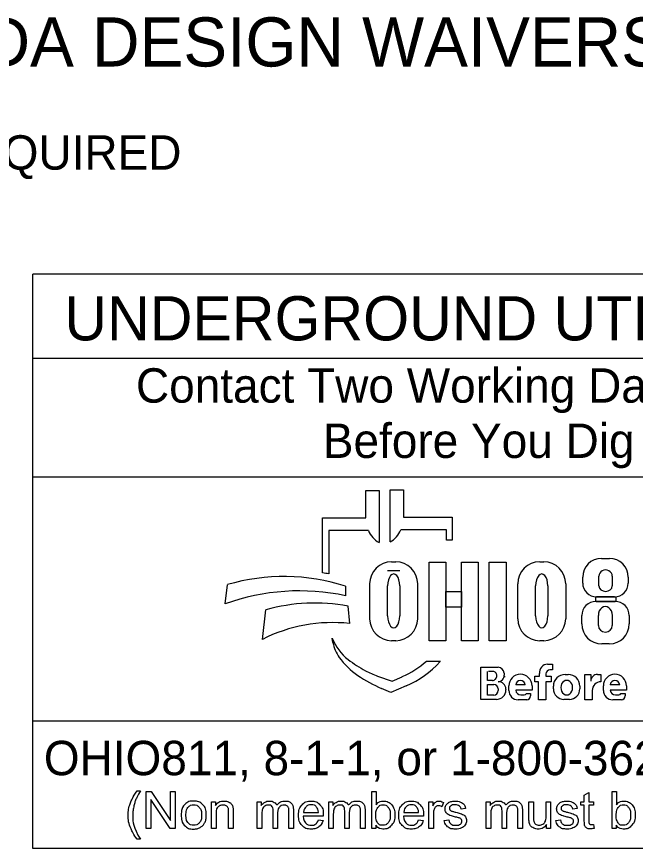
# Model space of a CAD drawing. Extents: x 0 to 34, y -2 to 22.
# Drawn here: x 2.311 to 4.831, y 2.143 to 5.529 of the extents above; entities that cross this region are included whole.
import ezdxf

# ---------------------------------------------------------------- set-up
doc = ezdxf.new("R2010")
doc.units = 0
doc.layers.add('SH_Data', color=7, linetype='Continuous')
doc.layers.add('SH_Text', color=7, linetype='Continuous')

msp = doc.modelspace()

# ---------------------------------------------------------------- linework, layer by layer
at = {"layer": 'SH_Data'}
for p, q in [((2.3775, 2.1428), (2.3775, 4.4803)), ((6.6275, 4.4803), (2.3775, 4.4803)), ((2.3775, 4.1387), (6.6275, 4.1387)), ((2.3775, 3.6553), (6.6275, 3.6553)), ((6.6275, 2.6607), (2.3775, 2.6607)), ((6.6275, 2.1428), (2.3775, 2.1428))]:
    msp.add_line(p, q, dxfattribs=at)
at = {"layer": 'SH_Text'}
for p, q in [((3.7335, 3.4883), (3.7335, 3.5998)), ((3.7335, 3.5998), (3.7872, 3.5998)), ((3.7872, 3.5998), (3.7872, 3.3877)), ((3.8329, 3.39), (3.8329, 3.6021)), ((3.8329, 3.6021), (3.8865, 3.6021)), ((3.8865, 3.6021), (3.8865, 3.4906)), ((3.5576, 3.2644), (3.5576, 3.4883)), ((3.5576, 3.4883), (3.7335, 3.4883)), ((3.8865, 3.4906), (4.0857, 3.4906)), ((4.0857, 3.4906), (4.0857, 3.3968)), ((3.5828, 3.4369), (3.5828, 3.26)), ((3.7439, 3.4369), (3.5828, 3.4369)), ((4.0625, 3.4392), (3.8761, 3.4392)), ((4.0625, 3.3968), (4.0625, 3.4392)), ((4.0857, 3.3968), (4.0625, 3.3968)), ((4.6931, 3.3231), (4.7258, 3.3231)), ((3.8385, 3.3091), (3.8551, 3.3091)), ((4.4416, 3.3091), (4.4581, 3.3091)), ((3.8718, 3.2721), (3.822, 3.2721)), ((4.683, 3.2111), (4.683, 3.2504)), ((4.7371, 3.2504), (4.7371, 3.2111)), ((3.7491, 3.0776), (3.7491, 3.2196)), ((3.9445, 3.2196), (3.9445, 3.0776)), ((4.3521, 3.0776), (4.3521, 3.2196)), ((4.5476, 3.2196), (4.5476, 3.0776)), ((4.6168, 3.2225), (4.6168, 3.2468)), ((4.8022, 3.2468), (4.8022, 3.2225)), ((3.1602, 3.1381), (3.1696, 3.2162)), ((3.6509, 3.2097), (3.6509, 3.1709)), ((3.822, 3.089), (3.822, 3.2114)), ((3.8718, 3.2114), (3.8718, 3.089)), ((4.425, 3.089), (4.425, 3.2114)), ((4.4748, 3.2114), (4.4748, 3.089)), ((4.7462, 3.1665), (4.6728, 3.1665)), ((3.6608, 3.1291), (3.6671, 3.0582)), ((4.671, 3.1482), (4.7483, 3.1482)), ((3.312, 2.9936), (3.3267, 3.1137)), ((4.6131, 3.0563), (4.6131, 3.0903)), ((4.6806, 3.0503), (4.6806, 3.0912)), ((4.7374, 3.0912), (4.7374, 3.0503)), ((4.8062, 3.0903), (4.8062, 3.0563)), ((3.5997, 2.9807), (3.5967, 2.9986)), ((3.8551, 2.9882), (3.8385, 2.9882)), ((4.4581, 2.9882), (4.4416, 2.9882)), ((4.7252, 2.9753), (4.6941, 2.9753)), ((3.98, 2.9048), (4.0375, 2.9048)), ((4.2013, 2.749), (4.2013, 2.8798)), ((4.2013, 2.8798), (4.2725, 2.8798)), ((4.4739, 2.8926), (4.4934, 2.8926)), ((4.4934, 2.8926), (4.4934, 2.8696)), ((3.7816, 2.8444), (3.841, 2.8239)), ((4.2293, 2.8263), (4.2293, 2.8632)), ((4.2545, 2.8632), (4.2332, 2.8632)), ((4.2963, 2.856), (4.2963, 2.8481)), ((4.4213, 2.8212), (4.4213, 2.8442)), ((4.4213, 2.8442), (4.4406, 2.8442)), ((4.4406, 2.8442), (4.4406, 2.8546)), ((4.4667, 2.8526), (4.4667, 2.8442)), ((4.4667, 2.8442), (4.4883, 2.8442)), ((4.4934, 2.8691), (4.4832, 2.8691)), ((4.4883, 2.8442), (4.4883, 2.8212)), ((4.5451, 2.8508), (4.5573, 2.8508)), ((4.6254, 2.7478), (4.6254, 2.8505)), ((4.6254, 2.8505), (4.6499, 2.8505)), ((4.6499, 2.8505), (4.6499, 2.8237)), ((4.6772, 2.8505), (4.691, 2.8505)), ((4.691, 2.8505), (4.691, 2.8209)), ((3.841, 2.8239), (3.8821, 2.8417)), ((4.2487, 2.8263), (4.2293, 2.8263)), ((4.4362, 2.8212), (4.4213, 2.8212)), ((4.4362, 2.7478), (4.4362, 2.8212)), ((4.4883, 2.8212), (4.4667, 2.8212)), ((4.4667, 2.8212), (4.4667, 2.7478)), ((3.835, 2.7769), (3.7976, 2.7934)), ((3.8983, 2.8044), (3.835, 2.7769)), ((4.2293, 2.7669), (4.2293, 2.8097)), ((4.2293, 2.8097), (4.2548, 2.8097)), ((4.2729, 2.7916), (4.2729, 2.7853)), ((4.3043, 2.7887), (4.3043, 2.7884)), ((4.3159, 2.7858), (4.3159, 2.8042)), ((4.3824, 2.8082), (4.3439, 2.8082)), ((4.4104, 2.7866), (4.344, 2.7866)), ((4.4104, 2.8042), (4.4104, 2.7866)), ((4.4973, 2.7922), (4.4973, 2.8029)), ((4.6051, 2.8029), (4.6051, 2.7922)), ((4.6559, 2.786), (4.6559, 2.7478)), ((4.7008, 2.7858), (4.7008, 2.8042)), ((4.7674, 2.8082), (4.7288, 2.8082)), ((4.7953, 2.7866), (4.7289, 2.7866)), ((4.7953, 2.8042), (4.7953, 2.7866)), ((4.265, 2.749), (4.2013, 2.749)), ((4.2546, 2.7669), (4.2293, 2.7669)), ((4.3892, 2.7478), (4.3538, 2.7478)), ((4.3649, 2.7673), (4.379, 2.7673)), ((4.3876, 2.7729), (4.4045, 2.7729)), ((4.4045, 2.7729), (4.4045, 2.7631)), ((4.4667, 2.7478), (4.4362, 2.7478)), ((4.5623, 2.7494), (4.5401, 2.7494)), ((4.6559, 2.7478), (4.6254, 2.7478)), ((4.7742, 2.7478), (4.7388, 2.7478)), ((4.7498, 2.7673), (4.7639, 2.7673)), ((4.7725, 2.7729), (4.7894, 2.7729)), ((4.7894, 2.7729), (4.7894, 2.7631))]:
    msp.add_line(p, q, dxfattribs=at)
for points in [[(3.991, 3.3081), (4.0589, 3.3081), (4.0589, 2.9881), (3.991, 2.9881)], [(4.1231, 3.3081), (4.1911, 3.3081), (4.1911, 2.9881), (4.1231, 2.9881)], [(4.2364, 3.3081), (4.3052, 3.3081), (4.3052, 2.9881), (4.2364, 2.9881)], [(4.0589, 3.1882), (4.1231, 3.1882), (4.1231, 3.1242), (4.0589, 3.1242)], [(4.6706, 3.1665), (4.7523, 3.1665), (4.7523, 3.1481), (4.6706, 3.1481)]]:
    msp.add_lwpolyline(points, close=True, dxfattribs=at)
for points in [[(2.8021, 2.3766), (2.8153, 2.3766)], [(2.8389, 2.2239), (2.8389, 2.3741), (2.8592, 2.3741), (2.9382, 2.2561), (2.9382, 2.3741), (2.9572, 2.3741), (2.9572, 2.2239), (2.9369, 2.2239), (2.8579, 2.3419), (2.8579, 2.2239), (2.8389, 2.2239)], [(3.7743, 2.2239), (3.7573, 2.2239), (3.7573, 2.3741), (3.7757, 2.3741), (3.7757, 2.3206)], [(4.6233, 2.2558), (4.6233, 2.3185), (4.6097, 2.3185), (4.6097, 2.3328), (4.6233, 2.3328), (4.6233, 2.3597), (4.6417, 2.3708), (4.6417, 2.3328), (4.6601, 2.3328), (4.6601, 2.3185), (4.6417, 2.3185), (4.6417, 2.2547)], [(4.7534, 2.2239), (4.7363, 2.2239), (4.7363, 2.3741), (4.7548, 2.3741), (4.7548, 2.3206)], [(3.1048, 2.2239), (3.1048, 2.3328), (3.1214, 2.3328), (3.1214, 2.3173)], [(3.2912, 2.2239), (3.2912, 2.3328), (3.3077, 2.3328), (3.3077, 2.3174)], [(3.5826, 2.2239), (3.5826, 2.3328), (3.5991, 2.3328), (3.5991, 2.3174)], [(3.9904, 2.2239), (3.9904, 2.3328), (4.007, 2.3328), (4.007, 2.3163)], [(4.0495, 2.3293), (4.043, 2.3122)], [(4.1394, 2.3046), (4.1213, 2.3022)], [(4.2236, 2.2239), (4.2236, 2.3328), (4.2401, 2.3328), (4.2401, 2.3174)], [(4.3979, 2.2654), (4.3979, 2.3328), (4.4164, 2.3328), (4.4164, 2.2724)], [(4.4676, 2.2745), (4.4676, 2.3328), (4.4861, 2.3328), (4.4861, 2.2239), (4.4696, 2.2239)], [(4.594, 2.3046), (4.5759, 2.3022)], [(3.1233, 2.2833), (3.1233, 2.2239), (3.1048, 2.2239)], [(3.1932, 2.2908), (3.1932, 2.2239), (3.1748, 2.2239), (3.1748, 2.2901)], [(3.3097, 2.2803), (3.3097, 2.2239), (3.2912, 2.2239)], [(3.3743, 2.2871), (3.3743, 2.2239), (3.3559, 2.2239), (3.3559, 2.2946)], [(3.4388, 2.2986), (3.4388, 2.2239), (3.4203, 2.2239), (3.4203, 2.2924)], [(3.56, 2.2736), (3.4788, 2.2736)], [(3.4799, 2.2887), (3.5406, 2.2887)], [(3.601, 2.2803), (3.601, 2.2239), (3.5826, 2.2239)], [(3.6657, 2.2871), (3.6657, 2.2239), (3.6473, 2.2239), (3.6473, 2.2946)], [(3.7301, 2.2986), (3.7301, 2.2239), (3.7117, 2.2239), (3.7117, 2.2924)], [(3.968, 2.2736), (3.8868, 2.2736)], [(3.8879, 2.2887), (3.9486, 2.2887)], [(4.0088, 2.2809), (4.0088, 2.2239), (3.9904, 2.2239)], [(4.242, 2.2803), (4.242, 2.2239), (4.2236, 2.2239)], [(4.3067, 2.2871), (4.3067, 2.2239), (4.2883, 2.2239), (4.2883, 2.2946)], [(4.3711, 2.2986), (4.3711, 2.2239), (4.3527, 2.2239), (4.3527, 2.2924)], [(3.5404, 2.2591), (3.5595, 2.2567)], [(3.7743, 2.2375), (3.7743, 2.2239)], [(3.9484, 2.2591), (3.9675, 2.2567)], [(4.053, 2.2564), (4.0712, 2.2593)], [(4.4696, 2.2239), (4.4696, 2.24)], [(4.5076, 2.2564), (4.5258, 2.2593)], [(4.6601, 2.2404), (4.6628, 2.2241)], [(4.7534, 2.2375), (4.7534, 2.2239)], [(2.8153, 2.1798), (2.8021, 2.1798)]]:
    msp.add_lwpolyline(points, dxfattribs=at)
for centre, radius, start, end in [((3.8353, 3.4736), 0.0985, 201.9296, 240.7469), ((3.7847, 3.476), 0.0985, 299.2531, 338.0704), ((4.6931, 3.2468), 0.0763, 90, 180), ((4.7258, 3.2468), 0.0763, 0, 90), ((3.8385, 3.2196), 0.0895, 90, 180), ((3.8551, 3.2196), 0.0895, 0, 90), ((4.4416, 3.2196), 0.0895, 90, 180), ((4.4581, 3.2196), 0.0895, 0, 90), ((3.4295, 2.4554), 0.8191, 79.2074, 81.0007), ((3.3997, 2.4302), 0.8191, 72.1402, 106.3144), ((4.6728, 3.2225), 0.056, 180, 270), ((4.7462, 3.2225), 0.056, 270, 0), ((3.4628, 2.2991), 0.8919, 77.8238, 109.8274), ((3.5267, 2.4094), 0.7322, 79.44, 105.8467), ((4.671, 3.0903), 0.0579, 90, 180), ((4.7483, 3.0903), 0.0579, 0, 90), ((3.5987, 2.4262), 0.6357, 83.8248, 116.8021), ((3.8385, 3.0776), 0.0895, 180, 270), ((3.8551, 3.0776), 0.0895, 270, 0), ((4.4416, 3.0776), 0.0895, 180, 270), ((4.4581, 3.0776), 0.0895, 270, 0), ((4.6941, 3.0563), 0.081, 180, 270), ((4.7252, 3.0563), 0.081, 270, 0), ((3.7841, 3.0707), 0.2008, 201.0457, 232.5314), ((3.741, 3.0048), 0.1433, 189.6817, 216.0884), ((3.8747, 3.1022), 0.3088, 216.0884, 235.7167), ((3.9766, 3.3219), 0.5173, 232.5314, 241.794), ((3.7387, 3.1722), 0.3602, 293.4582, 312.0712), ((3.7387, 3.1722), 0.401, 293.4582, 317.8286), ((4.2725, 2.856), 0.0238, 0, 90), ((4.4739, 2.859), 0.0335, 90, 187.5187), ((4.0412, 3.3465), 0.6044, 235.7167, 246.2325), ((3.8914, 3.1631), 0.3371, 241.794, 250.9821), ((4.2487, 2.845), 0.0187, 270, 2.0582), ((4.2505, 2.8463), 0.0169, 357.8325, 90), ((4.2721, 2.8453), 0.0243, 270, 6.6529), ((4.3631, 2.8042), 0.0473, 0, 180), ((4.4832, 2.8526), 0.0165, 90, 180), ((4.5451, 2.8029), 0.0478, 90, 180), ((4.5573, 2.8029), 0.0478, 0, 90), ((4.6768, 2.8237), 0.0269, 89.2449, 180), ((4.7481, 2.8042), 0.0473, 0, 180), ((4.2722, 2.7889), 0.0321, 4.0748, 90), ((4.2827, 2.8438), 0.0175, 347.4023, 0), ((4.3632, 2.8072), 0.0193, 2.9632, 177.0368), ((4.6908, 2.786), 0.0349, 89.6033, 180), ((4.7481, 2.8072), 0.0193, 2.9632, 177.0368), ((4.2546, 2.7853), 0.0184, 270, 0), ((4.2548, 2.7916), 0.0181, 0, 90), ((4.265, 2.7884), 0.0393, 270, 0), ((4.2714, 2.7887), 0.033, 0, 11.7502), ((4.3538, 2.7858), 0.038, 180, 270), ((4.3649, 2.7883), 0.021, 184.827, 270), ((4.5401, 2.7922), 0.0428, 180, 270), ((4.5623, 2.7922), 0.0428, 270, 0), ((4.7388, 2.7858), 0.038, 180, 270), ((4.7498, 2.7883), 0.021, 184.827, 270), ((4.379, 2.7767), 0.00938, 270, 335.9979), ((4.3892, 2.7631), 0.0152, 270, 0), ((4.7639, 2.7767), 0.00938, 270, 335.9979), ((4.7742, 2.7631), 0.0152, 270, 0)]:
    msp.add_arc(centre, radius, start, end, dxfattribs=at)
for centre, major_axis, ratio, start_param, end_param in [((3.8469, 3.2114), (0, 0.0484), 0.514403, 4.712389, 7.853982), ((4.4499, 3.2114), (0, 0.0484), 0.514403, 4.712389, 7.853982), ((4.71, 3.2504), (0.0271, 0), 0.969373, 0, 3.141593), ((4.71, 3.2111), (0.0271, 0), 0.818453, 3.141593, 6.283185), ((4.709, 3.0912), (0, 0.0358), 0.794529, 4.712389, 7.853982), ((3.8469, 3.089), (0, 0.0484), 0.514403, 1.570796, 4.712389), ((4.4499, 3.089), (0, 0.0484), 0.514403, 1.570796, 4.712389), ((4.709, 3.0503), (0.0284, 0), 0.959837, 3.141593, 6.283185), ((4.5517, 2.7976), (0, 0.029), 0.832186, 4.712389, 7.853982), ((4.5517, 2.7976), (0, 0.0302), 0.797287, 1.570796, 4.712389)]:
    msp.add_ellipse(centre, major_axis=major_axis, ratio=ratio, start_param=start_param, end_param=end_param, dxfattribs=at)
for points in [[(2.8021, 2.1798), (2.7869, 2.199), (2.7763, 2.2248), (2.7657, 2.2506), (2.7657, 2.2783), (2.7657, 2.3026), (2.7736, 2.325), (2.7829, 2.3509), (2.8021, 2.3766)], [(2.8153, 2.3766), (2.8029, 2.3553), (2.7989, 2.3462), (2.7927, 2.332), (2.7891, 2.3167), (2.7847, 2.2975), (2.7847, 2.2782), (2.7847, 2.2289), (2.8153, 2.1798)], [(2.9814, 2.2783), (2.9814, 2.3085), (2.9981, 2.3231), (3.0122, 2.3352), (3.0323, 2.3352), (3.0547, 2.3352), (3.069, 2.3205), (3.0832, 2.3058), (3.0832, 2.2799), (3.0832, 2.2589), (3.0769, 2.2469), (3.0706, 2.2348), (3.0586, 2.2282), (3.0466, 2.2215), (3.0323, 2.2215), (3.0095, 2.2215), (2.9954, 2.2362), (2.9814, 2.2508), (2.9814, 2.2783)], [(3.0003, 2.2783), (3.0003, 2.2574), (3.0094, 2.247), (3.0185, 2.2366), (3.0323, 2.2366), (3.046, 2.2366), (3.0551, 2.2471), (3.0642, 2.2575), (3.0642, 2.279), (3.0642, 2.2991), (3.0551, 2.3095), (3.0459, 2.3199), (3.0323, 2.3199), (3.0185, 2.3199), (3.0094, 2.3096), (3.0003, 2.2992), (3.0003, 2.2783)], [(3.1214, 2.3173), (3.1334, 2.3352), (3.156, 2.3352), (3.1659, 2.3352), (3.1741, 2.3316), (3.1823, 2.3281), (3.1864, 2.3224), (3.1905, 2.3166), (3.1922, 2.3087), (3.1932, 2.3036), (3.1932, 2.2908)], [(3.1748, 2.2901), (3.1748, 2.3013), (3.1726, 2.3069), (3.1705, 2.3125), (3.165, 2.3158), (3.1595, 2.3191), (3.1521, 2.3191), (3.1404, 2.3191), (3.1318, 2.3117), (3.1233, 2.3042), (3.1233, 2.2833)], [(3.3077, 2.3174), (3.3128, 2.3254), (3.3214, 2.3303), (3.3299, 2.3352), (3.3407, 2.3352), (3.3528, 2.3352), (3.3606, 2.3301), (3.3683, 2.3251), (3.3715, 2.3161), (3.3844, 2.3352), (3.4051, 2.3352), (3.4213, 2.3352), (3.43, 2.3262), (3.4388, 2.3172), (3.4388, 2.2986)], [(3.3559, 2.2946), (3.3559, 2.3069), (3.3514, 2.313), (3.3469, 2.3191), (3.3366, 2.3191), (3.3288, 2.3191), (3.3222, 2.315), (3.3156, 2.311), (3.3126, 2.3031), (3.3097, 2.2952), (3.3097, 2.2803)], [(3.4203, 2.2924), (3.4203, 2.3035), (3.4185, 2.3083), (3.4168, 2.3132), (3.412, 2.3162), (3.4073, 2.3191), (3.401, 2.3191), (3.3895, 2.3191), (3.3819, 2.3115), (3.3743, 2.3039), (3.3743, 2.2871)], [(3.5595, 2.2567), (3.555, 2.24), (3.5428, 2.2307), (3.5306, 2.2215), (3.5117, 2.2215), (3.4878, 2.2215), (3.4738, 2.2362), (3.4598, 2.2509), (3.4598, 2.2774), (3.4598, 2.3049), (3.474, 2.32), (3.4881, 2.3352), (3.5106, 2.3352), (3.5324, 2.3352), (3.5463, 2.3203), (3.5601, 2.3055), (3.5601, 2.2785), (3.5601, 2.2769), (3.56, 2.2736)], [(3.5406, 2.2887), (3.5394, 2.3025), (3.5337, 2.3094), (3.5249, 2.3201), (3.5108, 2.3201), (3.4981, 2.3201), (3.4894, 2.3115), (3.4808, 2.303), (3.4799, 2.2887)], [(3.5991, 2.3174), (3.6042, 2.3254), (3.6127, 2.3303), (3.6212, 2.3352), (3.6321, 2.3352), (3.6442, 2.3352), (3.6519, 2.3301), (3.6597, 2.3251), (3.6628, 2.3161), (3.6758, 2.3352), (3.6965, 2.3352), (3.7127, 2.3352), (3.7214, 2.3262), (3.7301, 2.3172), (3.7301, 2.2986)], [(3.6473, 2.2946), (3.6473, 2.3069), (3.6428, 2.313), (3.6383, 2.3191), (3.628, 2.3191), (3.6202, 2.3191), (3.6136, 2.315), (3.607, 2.311), (3.604, 2.3031), (3.601, 2.2952), (3.601, 2.2803)], [(3.7117, 2.2924), (3.7117, 2.3035), (3.7099, 2.3083), (3.7081, 2.3132), (3.7034, 2.3162), (3.6987, 2.3191), (3.6923, 2.3191), (3.6809, 2.3191), (3.6733, 2.3115), (3.6657, 2.3039), (3.6657, 2.2871)], [(3.7741, 2.2792), (3.7741, 2.2596), (3.7794, 2.2509), (3.7881, 2.2366), (3.8029, 2.2366), (3.815, 2.2366), (3.8238, 2.2471), (3.8326, 2.2576), (3.8326, 2.2784), (3.8326, 2.2998), (3.8241, 2.3099), (3.8157, 2.3201), (3.8038, 2.3201), (3.7917, 2.3201), (3.7829, 2.3096), (3.7741, 2.299), (3.7741, 2.2792)], [(3.7757, 2.3206), (3.7874, 2.3352), (3.8055, 2.3352), (3.8155, 2.3352), (3.8245, 2.3311), (3.8335, 2.3271), (3.8392, 2.3198), (3.845, 2.3124), (3.8483, 2.3021), (3.8516, 2.2918), (3.8516, 2.28), (3.8516, 2.252), (3.8378, 2.2368), (3.8239, 2.2215), (3.8046, 2.2215), (3.7853, 2.2215), (3.7743, 2.2375)], [(3.9675, 2.2567), (3.963, 2.24), (3.9508, 2.2307), (3.9386, 2.2215), (3.9196, 2.2215), (3.8958, 2.2215), (3.8818, 2.2362), (3.8678, 2.2509), (3.8678, 2.2774), (3.8678, 2.3049), (3.882, 2.32), (3.8961, 2.3352), (3.9186, 2.3352), (3.9404, 2.3352), (3.9543, 2.3203), (3.9681, 2.3055), (3.9681, 2.2785), (3.9681, 2.2769), (3.968, 2.2736)], [(3.9486, 2.2887), (3.9474, 2.3025), (3.9417, 2.3094), (3.9328, 2.3201), (3.9188, 2.3201), (3.9061, 2.3201), (3.8974, 2.3115), (3.8888, 2.303), (3.8879, 2.2887)], [(4.007, 2.3163), (4.0133, 2.3278), (4.0187, 2.3315), (4.0241, 2.3352), (4.0305, 2.3352), (4.0398, 2.3352), (4.0495, 2.3293)], [(4.043, 2.3122), (4.0363, 2.3162), (4.0295, 2.3162), (4.0235, 2.3162), (4.0187, 2.3125), (4.0139, 2.3089), (4.0119, 2.3024), (4.0088, 2.2926), (4.0088, 2.2809)], [(4.1213, 2.3022), (4.1201, 2.3106), (4.1142, 2.3153), (4.1083, 2.3201), (4.0975, 2.3201), (4.0848, 2.3201), (4.0794, 2.3159), (4.0739, 2.3116), (4.0739, 2.306), (4.0739, 2.3024), (4.0762, 2.2995), (4.0785, 2.2966), (4.0833, 2.2946), (4.086, 2.2936), (4.0996, 2.2899), (4.1192, 2.2847), (4.1269, 2.2813), (4.1347, 2.278), (4.1391, 2.2717), (4.1435, 2.2653), (4.1435, 2.2559), (4.1435, 2.2467), (4.1381, 2.2386), (4.1327, 2.2304), (4.1226, 2.226), (4.1124, 2.2215), (4.0996, 2.2215), (4.0784, 2.2215), (4.0672, 2.2303), (4.0561, 2.2391), (4.053, 2.2564)], [(4.0712, 2.2593), (4.0727, 2.2483), (4.0798, 2.2425), (4.0868, 2.2366), (4.0995, 2.2366), (4.1122, 2.2366), (4.1184, 2.2418), (4.1245, 2.247), (4.1245, 2.254), (4.1245, 2.2602), (4.1191, 2.2638), (4.1153, 2.2663), (4.1002, 2.2701), (4.0799, 2.2752), (4.072, 2.2789), (4.0642, 2.2827), (4.0601, 2.2893), (4.0561, 2.2959), (4.0561, 2.3038), (4.0561, 2.3111), (4.0594, 2.3173), (4.0628, 2.3235), (4.0685, 2.3276), (4.0728, 2.3308), (4.0803, 2.333), (4.0877, 2.3352), (4.0962, 2.3352), (4.109, 2.3352), (4.1187, 2.3315), (4.1284, 2.3278), (4.133, 2.3215), (4.1377, 2.3152), (4.1394, 2.3046)], [(4.2401, 2.3174), (4.2452, 2.3254), (4.2537, 2.3303), (4.2622, 2.3352), (4.2731, 2.3352), (4.2852, 2.3352), (4.2929, 2.3301), (4.3007, 2.3251), (4.3038, 2.3161), (4.3168, 2.3352), (4.3375, 2.3352), (4.3537, 2.3352), (4.3624, 2.3262), (4.3711, 2.3172), (4.3711, 2.2986)], [(4.2883, 2.2946), (4.2883, 2.3069), (4.2838, 2.313), (4.2793, 2.3191), (4.269, 2.3191), (4.2612, 2.3191), (4.2546, 2.315), (4.248, 2.311), (4.245, 2.3031), (4.242, 2.2952), (4.242, 2.2803)], [(4.3527, 2.2924), (4.3527, 2.3035), (4.3509, 2.3083), (4.3491, 2.3132), (4.3444, 2.3162), (4.3397, 2.3191), (4.3333, 2.3191), (4.3219, 2.3191), (4.3143, 2.3115), (4.3067, 2.3039), (4.3067, 2.2871)], [(4.5759, 2.3022), (4.5747, 2.3106), (4.5688, 2.3153), (4.5629, 2.3201), (4.5521, 2.3201), (4.5394, 2.3201), (4.5339, 2.3159), (4.5285, 2.3116), (4.5285, 2.306), (4.5285, 2.3024), (4.5308, 2.2995), (4.533, 2.2966), (4.5378, 2.2946), (4.5406, 2.2936), (4.5542, 2.2899), (4.5737, 2.2847), (4.5815, 2.2813), (4.5893, 2.278), (4.5937, 2.2717), (4.5981, 2.2653), (4.5981, 2.2559), (4.5981, 2.2467), (4.5927, 2.2386), (4.5873, 2.2304), (4.5772, 2.226), (4.567, 2.2215), (4.5542, 2.2215), (4.5329, 2.2215), (4.5218, 2.2303), (4.5107, 2.2391), (4.5076, 2.2564)], [(4.5258, 2.2593), (4.5273, 2.2483), (4.5343, 2.2425), (4.5414, 2.2366), (4.554, 2.2366), (4.5668, 2.2366), (4.5729, 2.2418), (4.5791, 2.247), (4.5791, 2.254), (4.5791, 2.2602), (4.5736, 2.2638), (4.5698, 2.2663), (4.5548, 2.2701), (4.5345, 2.2752), (4.5266, 2.2789), (4.5188, 2.2827), (4.5147, 2.2893), (4.5107, 2.2959), (4.5107, 2.3038), (4.5107, 2.3111), (4.514, 2.3173), (4.5173, 2.3235), (4.5231, 2.3276), (4.5274, 2.3308), (4.5348, 2.333), (4.5423, 2.3352), (4.5508, 2.3352), (4.5636, 2.3352), (4.5733, 2.3315), (4.583, 2.3278), (4.5876, 2.3215), (4.5922, 2.3152), (4.594, 2.3046)], [(4.7532, 2.2792), (4.7532, 2.2596), (4.7585, 2.2509), (4.7672, 2.2366), (4.782, 2.2366), (4.7941, 2.2366), (4.8029, 2.2471), (4.8116, 2.2576), (4.8116, 2.2784), (4.8116, 2.2998), (4.8032, 2.3099), (4.7948, 2.3201), (4.7828, 2.3201), (4.7708, 2.3201), (4.762, 2.3096), (4.7532, 2.299), (4.7532, 2.2792)], [(4.7548, 2.3206), (4.7664, 2.3352), (4.7846, 2.3352), (4.7946, 2.3352), (4.8036, 2.3311), (4.8125, 2.3271), (4.8183, 2.3198), (4.8241, 2.3124), (4.8274, 2.3021), (4.8306, 2.2918), (4.8306, 2.28), (4.8306, 2.252), (4.8168, 2.2368), (4.803, 2.2215), (4.7836, 2.2215), (4.7644, 2.2215), (4.7534, 2.2375)], [(3.4788, 2.2736), (3.4799, 2.2557), (3.489, 2.2462), (3.4981, 2.2366), (3.5117, 2.2366), (3.5219, 2.2366), (3.5291, 2.242), (3.5362, 2.2473), (3.5404, 2.2591)], [(3.8868, 2.2736), (3.8879, 2.2557), (3.897, 2.2462), (3.9061, 2.2366), (3.9197, 2.2366), (3.9299, 2.2366), (3.937, 2.242), (3.9442, 2.2473), (3.9484, 2.2591)], [(4.4164, 2.2724), (4.4164, 2.258), (4.4175, 2.253), (4.4192, 2.2457), (4.4249, 2.2416), (4.4305, 2.2374), (4.4388, 2.2374), (4.4471, 2.2374), (4.4543, 2.2417), (4.4616, 2.2459), (4.4646, 2.2533), (4.4676, 2.2606), (4.4676, 2.2745)], [(4.4696, 2.24), (4.4569, 2.2215), (4.4351, 2.2215), (4.4255, 2.2215), (4.4171, 2.2252), (4.4088, 2.2289), (4.4047, 2.2345), (4.4007, 2.2401), (4.3991, 2.2482), (4.3979, 2.2536), (4.3979, 2.2654)], [(4.6628, 2.2241), (4.655, 2.2224), (4.6488, 2.2224), (4.6388, 2.2224), (4.6333, 2.2256), (4.6278, 2.2288), (4.6255, 2.234), (4.6233, 2.2392), (4.6233, 2.2558)], [(4.6417, 2.2547), (4.6417, 2.2468), (4.6427, 2.2445), (4.6436, 2.2423), (4.6458, 2.2409), (4.648, 2.2396), (4.6521, 2.2396), (4.6551, 2.2396), (4.6601, 2.2404)]]:
    msp.add_open_spline(points, degree=3, dxfattribs=at)

# ---------------------------------------------------------------- texts
for s, height, p in [('ADA DESIGN WAIVERS', 0.2, (1.9944, 5.3256)), ('REQUIRED', 0.14, (1.9944, 4.9056)), ('UNDERGROUND UTILITIES', 0.18, (2.5057, 4.2106)), ('Contact Two Working Days', 0.14, (2.7972, 3.9571)), ('Before You Dig', 0.14, (3.5583, 3.7321)), ('OHIO811, 8-1-1, or 1-800-362-2764', 0.14, (2.422, 2.4406))]:
    msp.add_text(s, height=height, dxfattribs=at).set_placement(p)

doc.saveas('drawing.dxf')
